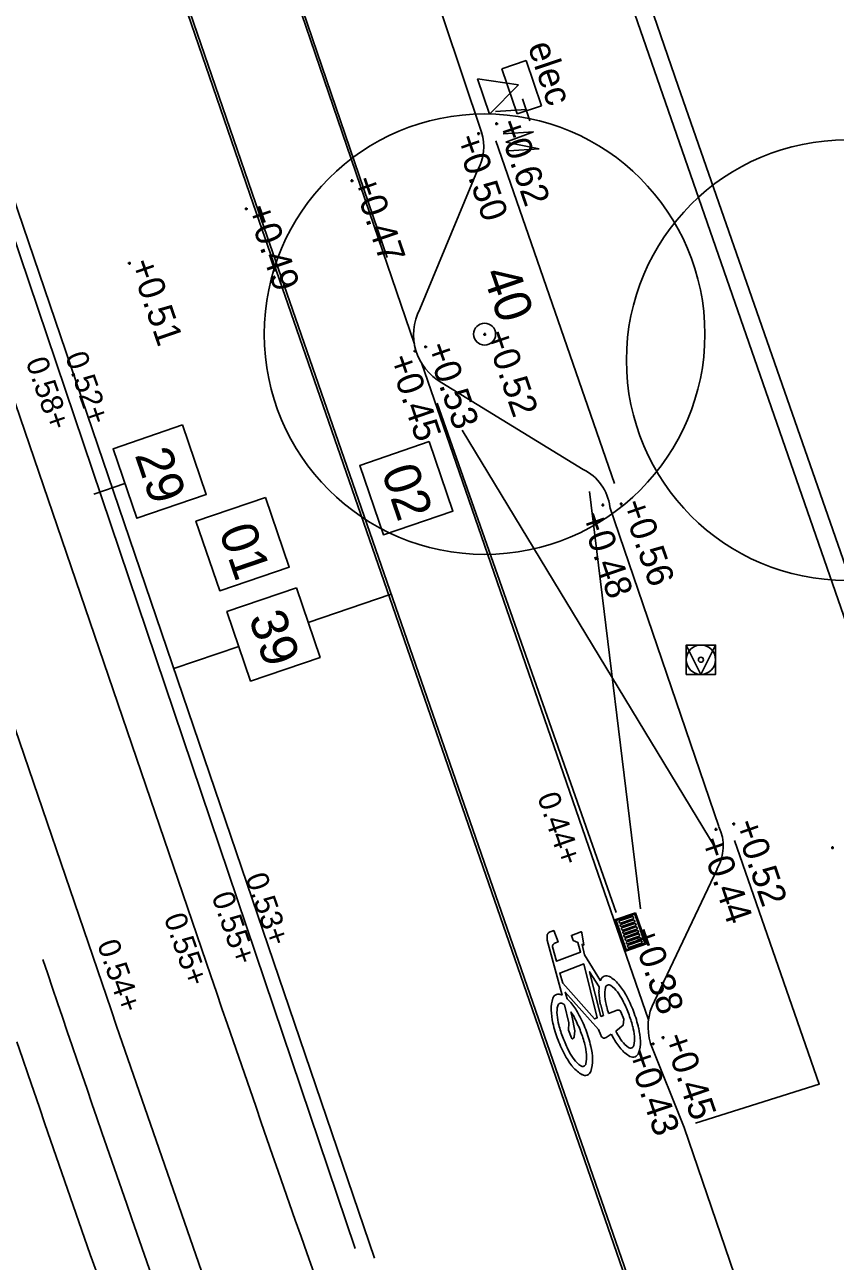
# Model space of a CAD drawing. Extents: x 122462 to 123306, y 485548 to 486417.
# Drawn here: x 122896.03 to 122907.06, y 485918.32 to 485935.16 of the extents above; entities that cross this region are included whole.
import ezdxf

# ---------------------------------------------------------------- set-up
doc = ezdxf.new("R2010")
doc.units = 0
for name, color, linetype in [('B meubilair trammast', 7, 'Continuous'), ('B nummers', 7, 'Continuous'), ('B-WE-GR-BOOM-S', 7, 'Continuous'), ('B-WE-GR-BOOM_BOOMDIAMETER-T25', 7, 'Continuous'), ('B-WE-IE-MEUBILAIR_ELECTRAKAST-S', 7, 'Continuous'), ('B-WE-IE-MEUBILAIR_WEGMEUBILAIR_VERKEERSBORD-S', 7, 'Continuous'), ('B-WE-IE-TERREINAFSCHEIDING_KUNSTMATIG_HEKWERK-G', 7, 'Continuous'), ('B-WE-OG-HOOGTEPUNT-S', 7, 'Continuous'), ('B-WE-RI-HWA_KOLK-S', 7, 'Continuous'), ('B-WE-VH-KANTOPSLUITING_OPSLUITBAND_100X200-G', 7, 'Continuous'), ('B-WE-VH-KANTOPSLUITING_TROTTOIRBAND_130 150-G', 7, 'Continuous'), ('B-WE-VH-MATERIAALGRENS_ASFALT-G', 7, 'Continuous'), ('B-WE-VW-MARKERING_LANGS_STREEP_11_010-G', 7, 'Continuous'), ('B-WE-VW-MARKERING_LANGS_STREEP_DOORGETROKKEN_010-G', 7, 'Continuous'), ('B-WE-VW-MARKERING_SYMBOOL-S', 7, 'Continuous'), ('Bestaand Hoogtemaat vast', 7, 'Continuous'), ('V markering 1-1 10 cm', 7, 'Continuous'), ('V markering ononderbroken streep 10 cm', 7, 'Continuous'), ('V materiaalscheiding algemeen', 7, 'Continuous'), ('V Rails', 7, 'Continuous'), ('V RWS-band 115-225x250 mm specie', 7, 'Continuous')]:
    doc.layers.add(name, color=color, linetype=linetype)

msp = doc.modelspace()

# ---------------------------------------------------------------- linework, layer by layer
at = {"layer": 'B meubilair trammast'}
for p, q in [((122902.754, 485934.339), (122902.193, 485934.42)), ((122902.193, 485934.42), (122902.355, 485933.938)), ((122902.355, 485933.938), (122902.754, 485934.339)), ((122902.807, 485934.15), (122902.907, 485933.85)), ((122902.857, 485934.001), (122902.44, 485933.974)), ((122902.542, 485933.671), (122902.958, 485933.697)), ((122902.958, 485933.697), (122902.581, 485933.556)), ((122902.581, 485933.556), (122903.035, 485933.468)), ((122903.035, 485933.468), (122902.619, 485933.442))]:
    msp.add_line(p, q, dxfattribs=at)
at = {"layer": 'B nummers'}
for p, q in [((122897.393, 485928.909), (122896.972, 485928.765)), ((122899.89, 485927.014), (122901.02, 485927.401)), ((122898.944, 485926.69), (122898.058, 485926.389))]:
    msp.add_line(p, q, dxfattribs=at)
for points in [[(122898.178, 485929.706), (122898.501, 485928.759), (122897.555, 485928.436), (122897.232, 485929.382)], [(122901.536, 485929.479), (122901.859, 485928.533), (122900.913, 485928.21), (122900.59, 485929.156)], [(122899.308, 485928.718), (122899.631, 485927.771), (122898.685, 485927.448), (122898.361, 485928.394)], [(122899.728, 485927.488), (122900.051, 485926.541), (122899.105, 485926.218), (122898.782, 485927.164)]]:
    msp.add_lwpolyline(points, close=True, dxfattribs=at)
at = {"layer": 'B-WE-GR-BOOM-S'}
for centre, radius in [((122902.29, 485930.943), 3), ((122907.222, 485930.589), 3), ((122902.29, 485930.943), 0.15), ((122902.29, 485930.943), 0.15)]:
    msp.add_circle(centre, radius, dxfattribs=at)
at = {"layer": 'B-WE-IE-MEUBILAIR_ELECTRAKAST-S'}
for p, q in [((122902.526, 485934.559), (122902.857, 485934.67)), ((122902.734, 485933.943), (122902.526, 485934.559)), ((122902.857, 485934.67), (122903.065, 485934.054)), ((122903.065, 485934.054), (122902.734, 485933.943))]:
    msp.add_line(p, q, dxfattribs=at)
at = {"layer": 'B-WE-IE-MEUBILAIR_WEGMEUBILAIR_VERKEERSBORD-S'}
for points in [[(122905.036, 485926.309), (122905.436, 485926.309), (122905.436, 485926.709), (122905.036, 485926.709)], [(122905.036, 485926.709), (122905.236, 485926.309), (122905.436, 485926.709)]]:
    msp.add_lwpolyline(points, close=True, dxfattribs=at)
for radius in [0.2, 0.0342]:
    msp.add_circle((122905.236, 485926.509), radius, dxfattribs=at)
at = {"layer": 'B-WE-IE-TERREINAFSCHEIDING_KUNSTMATIG_HEKWERK-G'}
msp.add_lwpolyline([(122913.109, 485920.57), (122912.323, 485922.986), (122909.28, 485921.833), (122904.924, 485934.32), (122900.18, 485948.116), (122898.098, 485954.01)], dxfattribs=at)
at = {"layer": 'B-WE-OG-HOOGTEPUNT-S'}
for p, q in [((122902.434, 485933.809), (122902.474, 485933.809)), ((122902.454, 485933.829), (122902.454, 485933.789)), ((122902.189, 485933.674), (122902.229, 485933.674)), ((122902.209, 485933.694), (122902.209, 485933.654)), ((122900.465, 485933.032), (122900.505, 485933.032)), ((122900.485, 485933.052), (122900.485, 485933.012)), ((122899.026, 485932.65), (122899.066, 485932.65)), ((122899.046, 485932.67), (122899.046, 485932.63)), ((122897.435, 485931.908), (122897.475, 485931.908)), ((122897.455, 485931.928), (122897.455, 485931.888)), ((122902.272, 485930.939), (122902.312, 485930.939)), ((122902.292, 485930.959), (122902.292, 485930.919)), ((122901.323, 485930.713), (122901.363, 485930.713)), ((122901.343, 485930.733), (122901.343, 485930.693)), ((122901.468, 485930.77), (122901.508, 485930.77)), ((122901.488, 485930.79), (122901.488, 485930.75)), ((122903.88, 485928.615), (122903.92, 485928.615)), ((122903.9, 485928.635), (122903.9, 485928.595)), ((122904.13, 485928.63), (122904.17, 485928.63)), ((122904.15, 485928.65), (122904.15, 485928.61)), ((122905.683, 485924.292), (122905.683, 485924.252)), ((122905.421, 485924.198), (122905.461, 485924.198)), ((122905.441, 485924.218), (122905.441, 485924.178)), ((122905.663, 485924.272), (122905.703, 485924.272)), ((122907.007, 485923.947), (122907.047, 485923.947)), ((122907.027, 485923.967), (122907.027, 485923.927)), ((122904.258, 485922.8), (122904.298, 485922.8)), ((122904.278, 485922.82), (122904.278, 485922.78)), ((122904.565, 485921.277), (122904.605, 485921.277)), ((122904.585, 485921.297), (122904.585, 485921.257)), ((122904.7, 485921.361), (122904.74, 485921.361)), ((122904.72, 485921.381), (122904.72, 485921.341))]:
    msp.add_line(p, q, dxfattribs=at)
at = {"layer": 'B-WE-RI-HWA_KOLK-S'}
for p, q in [((122904.062, 485922.964), (122904.346, 485923.062)), ((122904.21, 485922.539), (122904.062, 485922.964)), ((122904.081, 485922.955), (122904.337, 485923.043)), ((122904.219, 485922.558), (122904.081, 485922.955)), ((122904.337, 485923.043), (122904.474, 485922.646)), ((122904.346, 485923.062), (122904.493, 485922.637)), ((122904.21, 485922.539), (122904.493, 485922.637)), ((122904.219, 485922.558), (122904.474, 485922.646))]:
    msp.add_line(p, q, dxfattribs=at)
for points in [[(122904.122, 485922.938), (122904.126, 485922.927)], [(122904.302, 485923.011), (122904.128, 485922.951)], [(122904.139, 485922.92), (122904.313, 485922.981)], [(122904.319, 485922.964), (122904.145, 485922.903)], [(122904.155, 485922.873), (122904.329, 485922.933)], [(122904.319, 485922.993), (122904.315, 485923.005)], [(122904.335, 485922.946), (122904.331, 485922.958)], [(122904.138, 485922.891), (122904.142, 485922.879)], [(122904.155, 485922.843), (122904.159, 485922.832)], [(122904.335, 485922.916), (122904.161, 485922.856)], [(122904.171, 485922.826), (122904.346, 485922.886)], [(122904.171, 485922.796), (122904.175, 485922.785)], [(122904.351, 485922.869), (122904.177, 485922.809)], [(122904.188, 485922.779), (122904.362, 485922.839)], [(122904.368, 485922.822), (122904.194, 485922.762)], [(122904.204, 485922.731), (122904.378, 485922.792)], [(122904.384, 485922.775), (122904.21, 485922.714)], [(122904.352, 485922.899), (122904.348, 485922.91)], [(122904.368, 485922.852), (122904.364, 485922.863)], [(122904.384, 485922.804), (122904.38, 485922.816)], [(122904.401, 485922.757), (122904.397, 485922.769)], [(122904.188, 485922.749), (122904.191, 485922.738)], [(122904.204, 485922.702), (122904.208, 485922.69)], [(122904.22, 485922.654), (122904.224, 485922.643)], [(122904.221, 485922.684), (122904.395, 485922.744)], [(122904.401, 485922.727), (122904.226, 485922.667)], [(122904.237, 485922.637), (122904.411, 485922.697)], [(122904.237, 485922.607), (122904.241, 485922.596)], [(122904.417, 485922.68), (122904.243, 485922.62)], [(122904.253, 485922.59), (122904.427, 485922.65)], [(122904.417, 485922.71), (122904.413, 485922.721)], [(122904.434, 485922.663), (122904.43, 485922.674)]]:
    msp.add_lwpolyline(points, dxfattribs=at)
for centre, start, end in [((122904.131, 485922.941), 109.1123, 199.1123), ((122904.135, 485922.93), 199.1123, 289.1123), ((122904.306, 485923.002), 19.1123, 109.1123), ((122904.309, 485922.99), 289.1123, 19.1123), ((122904.322, 485922.954), 19.1123, 109.1123), ((122904.326, 485922.943), 289.1123, 19.1123), ((122904.148, 485922.894), 109.1123, 199.1123), ((122904.152, 485922.883), 199.1123, 289.1123), ((122904.164, 485922.847), 109.1123, 199.1123), ((122904.168, 485922.835), 199.1123, 289.1123), ((122904.181, 485922.799), 109.1123, 199.1123), ((122904.185, 485922.788), 199.1123, 289.1123), ((122904.197, 485922.752), 109.1123, 199.1123), ((122904.338, 485922.907), 19.1123, 109.1123), ((122904.342, 485922.896), 289.1123, 19.1123), ((122904.355, 485922.86), 19.1123, 109.1123), ((122904.359, 485922.848), 289.1123, 19.1123), ((122904.371, 485922.813), 19.1123, 109.1123), ((122904.375, 485922.801), 289.1123, 19.1123), ((122904.387, 485922.765), 19.1123, 109.1123), ((122904.391, 485922.754), 289.1123, 19.1123), ((122904.201, 485922.741), 199.1123, 289.1123), ((122904.213, 485922.705), 109.1123, 199.1123), ((122904.217, 485922.694), 199.1123, 289.1123), ((122904.23, 485922.658), 109.1123, 199.1123), ((122904.234, 485922.646), 199.1123, 289.1123), ((122904.246, 485922.61), 109.1123, 199.1123), ((122904.25, 485922.599), 199.1123, 289.1123), ((122904.404, 485922.718), 19.1123, 109.1123), ((122904.408, 485922.707), 289.1123, 19.1123), ((122904.42, 485922.671), 19.1123, 109.1123), ((122904.424, 485922.659), 289.1123, 19.1123)]:
    msp.add_arc(centre, 0.01, start, end, dxfattribs=at)
at = {"layer": 'B-WE-VH-KANTOPSLUITING_OPSLUITBAND_100X200-G'}
for points in [[(122913.961, 485923.465), (122909.075, 485921.649), (122904.526, 485934.752), (122901.455, 485943.609), (122897.901, 485953.916)], [(122904.058, 485928.911), (122902.444, 485933.576)], [(122905.164, 485920.198), (122906.847, 485920.728), (122905.695, 485924.046)]]:
    msp.add_lwpolyline(points, dxfattribs=at)
at = {"layer": 'B-WE-VH-KANTOPSLUITING_TROTTOIRBAND_130 150-G'}
for points in [[(122902.25, 485933.693), (122900.962, 485937.531)], [(122901.41, 485931.285), (122902.195, 485933.177)], [(122903.632, 485929.101), (122901.71, 485930.282)], [(122905.48, 485924.235), (122903.996, 485928.588)], [(122904.603, 485921.86), (122905.455, 485923.657)], [(122906.372, 485916.137), (122905.006, 485920.138), (122904.551, 485921.281)]]:
    msp.add_lwpolyline(points, dxfattribs=at)
for centre, radius, start, end in [((122901.638, 485933.497), 0.643, 330.1718, 17.7752), ((122902.072, 485930.936), 0.748, 152.2383, 241.0358), ((122903.342, 485928.511), 0.658, 6.7973, 63.874), ((122904.93, 485923.969), 0.61, 329.3054, 25.8325), ((122905.265, 485921.509), 0.749, 152.0724, 197.7337)]:
    msp.add_arc(centre, radius, start, end, dxfattribs=at)
at = {"layer": 'B-WE-VH-MATERIAALGRENS_ASFALT-G'}
msp.add_line((122904.522, 485921.603), (122901.43, 485930.552), dxfattribs=at)
msp.add_lwpolyline([(122901.335, 485930.807), (122898.446, 485939.272)], dxfattribs=at)
at = {"layer": 'B-WE-VW-MARKERING_LANGS_STREEP_11_010-G'}
for points in [[(122900.966, 485931.989), (122898.927, 485937.963)], [(122904.08, 485923.066), (122901.646, 485930.005)]]:
    msp.add_lwpolyline(points, dxfattribs=at)
at = {"layer": 'B-WE-VW-MARKERING_LANGS_STREEP_DOORGETROKKEN_010-G'}
for points in [[(122901.986, 485929.636), (122905.445, 485923.928)], [(122904.415, 485923.115), (122903.718, 485928.8)]]:
    msp.add_lwpolyline(points, dxfattribs=at)
at = {"layer": 'B-WE-VW-MARKERING_SYMBOOL-S'}
for points in [[(122903.197, 485922.805), (122903.231, 485922.819), (122903.29, 485922.664), (122903.256, 485922.651)], [(122903.213, 485922.596), (122903.269, 485922.401), (122903.598, 485922.527), (122903.558, 485922.658), (122903.498, 485922.685), (122903.472, 485922.754), (122903.592, 485922.799)], [(122903.616, 485922.789), (122903.64, 485922.621), (122903.617, 485922.632), (122903.652, 485922.488), (122903.868, 485922.136)], [(122903.348, 485921.938), (122903.144, 485922.687), (122903.141, 485922.745)], [(122903.911, 485921.664), (122903.874, 485921.65), (122903.72, 485922.259), (122903.851, 485922.052)], [(122903.414, 485921.89), (122903.388, 485921.98), (122903.843, 485921.474), (122903.874, 485921.394)], [(122903.474, 485921.36), (122903.435, 485921.463), (122903.436, 485921.561), (122903.378, 485921.808)], [(122903.465, 485921.712), (122903.485, 485921.639), (122903.517, 485921.454), (122903.509, 485921.373)], [(122903.979, 485921.69), (122904.097, 485921.735)], [(122904.144, 485921.714), (122904.184, 485921.611), (122904.175, 485921.53), (122904.078, 485921.449)], [(122903.945, 485921.363), (122904.016, 485921.409)]]:
    msp.add_lwpolyline(points, dxfattribs=at)
msp.add_lwpolyline([(122903.354, 485922.101), (122903.788, 485921.617), (122903.823, 485921.63), (122903.64, 485922.366), (122903.314, 485922.241)], close=True, dxfattribs=at)
for centre, radius, start, end in [((122903.199, 485922.747), 0.058, 92.4836, 182.4836), ((122903.6, 485922.787), 0.0154, 8.3898, 123.4474), ((122903.279, 485922.589), 0.0666, 110.9186, 173.865), ((122904.303, 485922.002), 0.455, 161.2298, 162.7912), ((122903.949, 485922.122), 0.0814, 110.9186, 161.2298), ((122903.949, 485922.122), 0.0814, 60.6074, 110.9186), ((122903.766, 485921.797), 0.455, 39.889, 60.6074), ((122903.386, 485921.479), 0.95, 29.0222, 39.889), ((122903.298, 485921.873), 0.0814, 110.9186, 161.2298), ((122903.298, 485921.873), 0.0814, 60.6074, 110.9186), ((122903.114, 485921.548), 0.455, 59.0459, 60.6074), ((122904.303, 485922.002), 0.455, 173.7044, 181.9482), ((122904.797, 485922.019), 0.95, 181.9482, 192.8149), ((122904.321, 485921.956), 0.393, 166.8607, 185.2763), ((122904.805, 485922.001), 0.88, 185.2763, 194.303), ((122903.982, 485922.035), 0.0458, 110.9186, 166.8607), ((122903.982, 485922.035), 0.0458, 54.9765, 110.9186), ((122903.783, 485921.751), 0.393, 36.5608, 54.9765), ((122903.392, 485921.461), 0.88, 27.5342, 36.5608), ((122902.725, 485921.113), 1.705, 20.9186, 29.0222), ((122903.651, 485921.753), 0.455, 161.2298, 181.9482), ((122903.669, 485921.707), 0.393, 166.8607, 185.2763), ((122903.331, 485921.786), 0.0458, 110.9186, 166.8607), ((122903.331, 485921.786), 0.0458, 54.9765, 110.9186), ((122903.131, 485921.502), 0.393, 51.1632, 54.9765), ((122903.114, 485921.548), 0.455, 39.889, 48.7915), ((122902.735, 485921.23), 0.95, 29.0222, 39.889), ((122905.534, 485922.186), 1.705, 192.8149, 197.8343), ((122905.538, 485922.188), 1.636, 194.303, 197.7044), ((122902.721, 485921.111), 1.636, 20.9186, 27.5342), ((122904.146, 485921.77), 0.95, 181.9482, 192.8149), ((122904.154, 485921.752), 0.88, 185.2763, 194.303), ((122902.741, 485921.212), 0.88, 27.5342, 34.6153), ((122902.07, 485920.862), 1.636, 20.9186, 27.5342), ((122902.074, 485920.864), 1.705, 20.9186, 29.0222), ((122904.11, 485921.701), 0.0367, 20.9186, 110.9186), ((122902.721, 485921.111), 1.636, 14.303, 20.9186), ((122902.725, 485921.113), 1.705, 12.8149, 20.9186), ((122904.883, 485921.937), 1.705, 192.8149, 200.9186), ((122904.887, 485921.939), 1.636, 194.303, 200.9186), ((122902.07, 485920.862), 1.636, 14.303, 20.9186), ((122902.074, 485920.864), 1.705, 12.8149, 20.9186), ((122905.538, 485922.188), 1.636, 206.8243, 207.5342), ((122904.867, 485921.838), 0.88, 207.5342, 216.5608), ((122903.454, 485921.298), 0.88, 5.2763, 14.303), ((122903.462, 485921.28), 0.95, 1.9482, 12.8149), ((122904.883, 485921.937), 1.705, 200.9186, 209.0222), ((122904.887, 485921.939), 1.636, 200.9186, 207.5342), ((122903.488, 485921.358), 0.0137, 174.3535, 317.4836), ((122903.468, 485921.377), 0.041, 317.4836, 354.3535), ((122902.803, 485921.049), 0.88, 5.2763, 14.303), ((122902.811, 485921.031), 0.95, 1.9482, 12.8149), ((122903.919, 485921.402), 0.0463, 188.7674, 303.0697), ((122905.534, 485922.186), 1.705, 207.1097, 209.0222), ((122904.873, 485921.82), 0.95, 209.0222, 219.889), ((122904.476, 485921.548), 0.393, 216.5608, 234.9765), ((122904.277, 485921.264), 0.0458, 290.9186, 346.8607), ((122903.939, 485921.343), 0.393, 346.8607, 5.2763), ((122903.957, 485921.297), 0.455, 341.2298, 1.9482), ((122904.222, 485921.571), 0.95, 209.0222, 219.889), ((122904.216, 485921.589), 0.88, 207.5342, 216.5608), ((122903.287, 485921.094), 0.393, 346.8607, 5.2763), ((122904.493, 485921.502), 0.455, 219.889, 240.6074), ((122904.277, 485921.264), 0.0458, 234.9765, 290.9186), ((122904.31, 485921.177), 0.0814, 240.6074, 290.9186), ((122904.31, 485921.177), 0.0814, 290.9186, 341.2298), ((122903.842, 485921.253), 0.455, 219.889, 240.6074), ((122903.825, 485921.299), 0.393, 216.5608, 234.9765), ((122903.626, 485921.015), 0.0458, 234.9765, 290.9186), ((122903.626, 485921.015), 0.0458, 290.9186, 346.8607), ((122903.305, 485921.048), 0.455, 341.2298, 1.9482), ((122903.659, 485920.928), 0.0814, 240.6074, 290.9186), ((122903.659, 485920.928), 0.0814, 290.9186, 341.2298)]:
    msp.add_arc(centre, radius, start, end, dxfattribs=at)
at = {"layer": 'V markering 1-1 10 cm'}
msp.add_lwpolyline([(122861.268, 486043.255), (122864.477, 486033.82), (122868.105, 486023.234), (122872.215, 486011.133), (122877.675, 485994.999), (122880.312, 485987.313), (122885.038, 485973.513), (122892.674, 485951.631), (122899.173, 485932.732), (122905.905, 485913.305)], dxfattribs=at)
msp.add_arc((123301.543, 486059.577), 427.846, 198.69687, 200.47426, dxfattribs=at)
at = {"layer": 'V markering ononderbroken streep 10 cm'}
msp.add_lwpolyline([(122900.793, 485918.356), (122895.862, 485932.839), (122890.421, 485948.745), (122886.073, 485961.479), (122881.891, 485973.721)], dxfattribs=at)
at = {"layer": 'V materiaalscheiding algemeen'}
msp.add_lwpolyline([(122861.232, 486043.247), (122864.442, 486033.808), (122868.07, 486023.222), (122872.18, 486011.121), (122877.64, 485994.987), (122880.277, 485987.301), (122885.003, 485973.501), (122892.639, 485951.618), (122899.138, 485932.72), (122905.87, 485913.293)], dxfattribs=at)
at = {"layer": 'V Rails'}
for p, q in [((122859.04, 486037.86), (122898.563, 485922.205)), ((122857.682, 486037.396), (122897.205, 485921.741))]:
    msp.add_line(p, q, dxfattribs=at)
for radius, end in [(499.283, 199.72946), (500.718, 199.72865), (502.073, 199.72789), (503.508, 199.72709)]:
    msp.add_arc((123371.02, 486083.659), radius, 198.86698, end, dxfattribs=at)
at = {"layer": 'V RWS-band 115-225x250 mm specie'}
msp.add_lwpolyline([(122881.712, 485973.732), (122885.936, 485961.375), (122890.294, 485948.692), (122895.718, 485932.752), (122900.529, 485918.488)], dxfattribs=at)

# ---------------------------------------------------------------- texts
at = {"layer": 'B nummers'}
for s, p in [('29', (122897.524, 485929.299)), ('02', (122900.882, 485929.073)), ('01', (122898.67, 485928.264)), ('39', (122899.074, 485927.082))]:
    msp.add_text(s, height=0.5, rotation=288.867, dxfattribs=at).set_placement(p)
at = {"layer": 'B-WE-GR-BOOM_BOOMDIAMETER-T25'}
msp.add_text('40', height=0.5, rotation=288.851, dxfattribs=at).set_placement((122902.258, 485931.77))
at = {"layer": 'B-WE-IE-MEUBILAIR_ELECTRAKAST-S'}
msp.add_text('elec', height=0.36, rotation=288.5573, dxfattribs=at).set_placement((122902.875, 485934.866))
at = {"layer": 'B-WE-OG-HOOGTEPUNT-S'}
for s, rotation, p in [('+0.62', 289, (122902.454, 485933.809)), ('+0.50', 288.851, (122901.886, 485933.604)), ('+0.47', 289, (122900.485, 485933.032)), ('+0.49', 289, (122899.046, 485932.65)), ('+0.51', 289, (122897.455, 485931.908)), ('+0.52', 289, (122902.292, 485930.939)), ('+0.53', 289, (122901.488, 485930.77)), ('+0.45', 288.851, (122900.977, 485930.606)), ('+0.56', 289, (122904.15, 485928.63)), ('+0.48', 288.851, (122903.588, 485928.465)), ('+0.52', 289, (122905.683, 485924.272)), ('+0.44', 288.851, (122905.213, 485924.034)), ('+0.38', 289, (122904.278, 485922.8)), ('+0.45', 289, (122904.72, 485921.361)), ('+0.43', 288.851, (122904.223, 485921.147))]:
    msp.add_text(s, height=0.36, rotation=rotation, dxfattribs=at).set_placement(p)
at = {"layer": 'Bestaand Hoogtemaat vast'}
for s, rotation, p in [('0.52+', 289.2135, (122896.577, 485930.645)), ('0.58+', 289.2135, (122896.039, 485930.57)), ('0.44+', 289.0343, (122903.004, 485924.644)), ('0.53+', 289.2221, (122899.029, 485923.546)), ('0.55+', 289.2221, (122898.57, 485923.289)), ('0.55+', 289.2221, (122897.92, 485922.997)), ('0.54+', 289.2221, (122897.011, 485922.637))]:
    msp.add_text(s, height=0.3, rotation=rotation, dxfattribs=at).set_placement(p)

doc.saveas('drawing.dxf')
